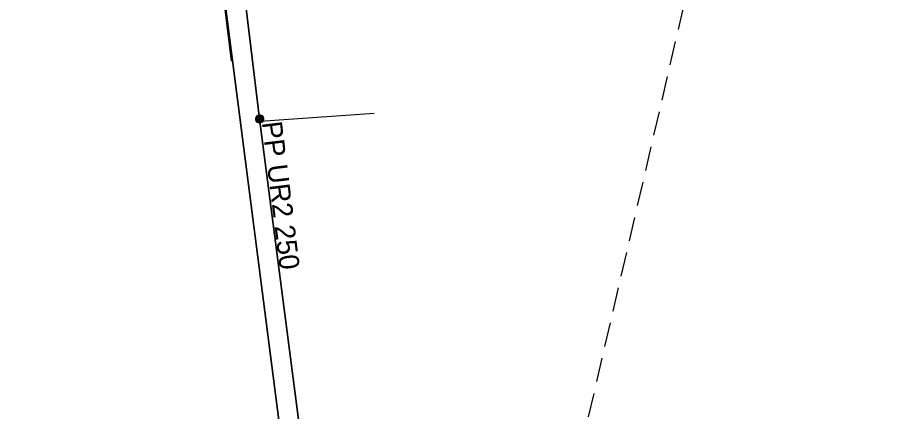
# Model space of a CAD drawing. Extents: x -866761 to -866592, y -1013996 to -1013877.
# Drawn here: x -866639.65 to -866591.97, y -1013957.66 to -1013936.05 of the extents above; entities that cross this region are included whole.
import ezdxf

# ---------------------------------------------------------------- set-up
doc = ezdxf.new("R2010")
doc.units = 0
doc.header["$LTSCALE"] = 0.44
doc.linetypes.add('MEDIUM_DASHED', pattern=[4.5, 3, -1.5])
for name, color, linetype, lineweight in [('1', 7, 'Continuous', 35), ('12', 7, 'Continuous', 13), ('21', 7, 'Continuous', 35), ('3', 7, 'Continuous', 25), ('62', 7, 'MEDIUM_DASHED', 25)]:
    doc.layers.add(name, color=color, linetype=linetype, lineweight=lineweight)

msp = doc.modelspace()

# ---------------------------------------------------------------- linework, layer by layer
at = {"layer": '1'}
msp.add_lwpolyline([(-866621.036, -1013976.325), (-866622.91, -1013968.373), (-866626.376, -1013941.619), (-866627.386, -1013933.289), (-866629.697, -1013910.45), (-866632.18, -1013888.99), (-866632.46, -1013887.48), (-866632.668, -1013884.429)], dxfattribs=at)
at = {"layer": '12'}
for points in [[(-866626.145, -1013941.619), (-866626.151, -1013941.567), (-866626.168, -1013941.517), (-866626.197, -1013941.473), (-866626.234, -1013941.436), (-866626.279, -1013941.409), (-866626.329, -1013941.392), (-866626.382, -1013941.388), (-866626.434, -1013941.395), (-866626.483, -1013941.414), (-866626.526, -1013941.443), (-866626.562, -1013941.482), (-866626.588, -1013941.527), (-866626.604, -1013941.578), (-866626.607, -1013941.63), (-866626.599, -1013941.682), (-866626.579, -1013941.731), (-866626.548, -1013941.774), (-866626.509, -1013941.808), (-866626.463, -1013941.834), (-866626.412, -1013941.848), (-866626.359, -1013941.85), (-866626.308, -1013941.84), (-866626.26, -1013941.819), (-866626.217, -1013941.788), (-866626.183, -1013941.747), (-866626.159, -1013941.701), (-866626.147, -1013941.65)], [(-866626.175, -1013941.619), (-866626.181, -1013941.57), (-866626.198, -1013941.524), (-866626.226, -1013941.484), (-866626.263, -1013941.452), (-866626.307, -1013941.43), (-866626.355, -1013941.419), (-866626.404, -1013941.419), (-866626.451, -1013941.432), (-866626.494, -1013941.456), (-866626.53, -1013941.489), (-866626.557, -1013941.53), (-866626.573, -1013941.577), (-866626.577, -1013941.626), (-866626.57, -1013941.674), (-866626.551, -1013941.719), (-866626.521, -1013941.759), (-866626.483, -1013941.79), (-866626.439, -1013941.81), (-866626.391, -1013941.82), (-866626.342, -1013941.818), (-866626.295, -1013941.803), (-866626.252, -1013941.778), (-866626.218, -1013941.744), (-866626.192, -1013941.702), (-866626.178, -1013941.655)], [(-866626.205, -1013941.619), (-866626.211, -1013941.574), (-866626.228, -1013941.532), (-866626.256, -1013941.497), (-866626.292, -1013941.47), (-866626.334, -1013941.453), (-866626.379, -1013941.448), (-866626.424, -1013941.454), (-866626.465, -1013941.473), (-866626.5, -1013941.501), (-866626.527, -1013941.538), (-866626.543, -1013941.58), (-866626.547, -1013941.625), (-866626.54, -1013941.67), (-866626.521, -1013941.711), (-866626.492, -1013941.745), (-866626.455, -1013941.771), (-866626.412, -1013941.787), (-866626.367, -1013941.79), (-866626.322, -1013941.782), (-866626.282, -1013941.762), (-866626.248, -1013941.733), (-866626.222, -1013941.695), (-866626.208, -1013941.652)], [(-866626.235, -1013941.619), (-866626.24, -1013941.578), (-866626.258, -1013941.541), (-866626.285, -1013941.51), (-866626.32, -1013941.489), (-866626.36, -1013941.478), (-866626.401, -1013941.48), (-866626.44, -1013941.493), (-866626.474, -1013941.517), (-866626.499, -1013941.549), (-866626.514, -1013941.587), (-866626.517, -1013941.628), (-866626.509, -1013941.668), (-866626.489, -1013941.704), (-866626.46, -1013941.733), (-866626.423, -1013941.752), (-866626.383, -1013941.76), (-866626.342, -1013941.756), (-866626.304, -1013941.741), (-866626.272, -1013941.715), (-866626.249, -1013941.681), (-866626.236, -1013941.642)], [(-866626.265, -1013941.619), (-866626.27, -1013941.583), (-866626.288, -1013941.551), (-866626.314, -1013941.526), (-866626.348, -1013941.511), (-866626.384, -1013941.508), (-866626.419, -1013941.516), (-866626.45, -1013941.536), (-866626.473, -1013941.564), (-866626.486, -1013941.598), (-866626.486, -1013941.635), (-866626.475, -1013941.67), (-866626.454, -1013941.699), (-866626.424, -1013941.72), (-866626.389, -1013941.73), (-866626.352, -1013941.728), (-866626.318, -1013941.714), (-866626.291, -1013941.691), (-866626.272, -1013941.659), (-866626.265, -1013941.624)], [(-866626.295, -1013941.619), (-866626.3, -1013941.588), (-866626.317, -1013941.562), (-866626.343, -1013941.545), (-866626.373, -1013941.538), (-866626.404, -1013941.542), (-866626.431, -1013941.559), (-866626.449, -1013941.583), (-866626.457, -1013941.614), (-866626.453, -1013941.644), (-866626.438, -1013941.672), (-866626.414, -1013941.691), (-866626.384, -1013941.7), (-866626.353, -1013941.697), (-866626.325, -1013941.683), (-866626.305, -1013941.659), (-866626.295, -1013941.63)], [(-866626.325, -1013941.619), (-866626.33, -1013941.595), (-866626.347, -1013941.577), (-866626.37, -1013941.568), (-866626.394, -1013941.571), (-866626.415, -1013941.585), (-866626.426, -1013941.607), (-866626.426, -1013941.632), (-866626.414, -1013941.653), (-866626.394, -1013941.667), (-866626.369, -1013941.67), (-866626.346, -1013941.661), (-866626.33, -1013941.643)], [(-866626.355, -1013941.619), (-866626.36, -1013941.604), (-866626.375, -1013941.598), (-866626.39, -1013941.602), (-866626.397, -1013941.616), (-866626.393, -1013941.631), (-866626.38, -1013941.64), (-866626.365, -1013941.637), (-866626.355, -1013941.625)]]:
    msp.add_lwpolyline(points, close=True, dxfattribs=at)
at = {"layer": '21'}
msp.add_lwpolyline([(-866627.91, -1013938.45), (-866629.08, -1013928.9), (-866624.31, -1013965.933), (-866624.165, -1013966.919), (-866622.957, -1013974.98)], dxfattribs=at)
at = {"layer": '3'}
msp.add_line((-866626.345, -1013941.74), (-866620.1, -1013941.311), dxfattribs=at)
at = {"layer": '62'}
msp.add_lwpolyline([(-866747.317, -1013876.568), (-866591.969, -1013887.219), (-866617.09, -1013995.541), (-866760.581, -1013983.282)], close=True, dxfattribs=at)

# ---------------------------------------------------------------- texts
at = {"layer": '1'}
msp.add_text('PP UR2 250', height=1.1, rotation=277, dxfattribs=at).set_placement((-866626.256, -1013941.814))

doc.saveas('drawing.dxf')
